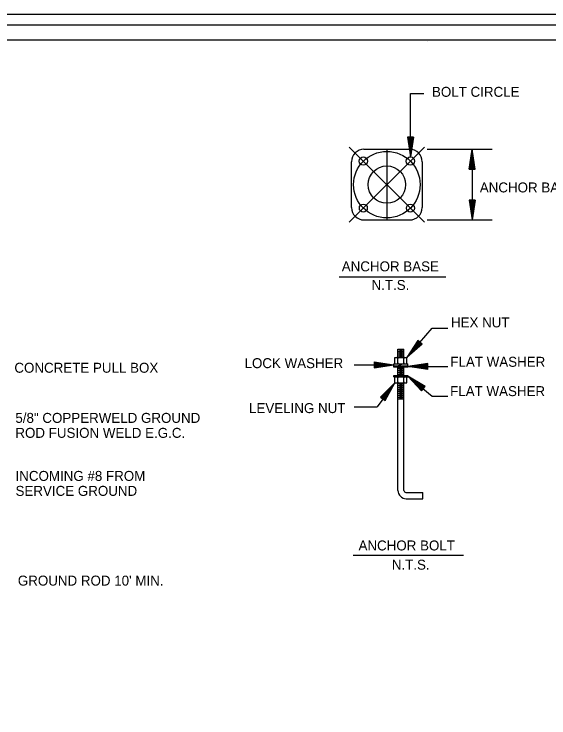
# Model space of a CAD drawing. Extents: x 1695551 to 1695718, y 544410 to 544516.
# Drawn here: x 1695602.6 to 1695642.8, y 544463.3 to 544516.2 of the extents above; entities that cross this region are included whole.
import ezdxf

# ---------------------------------------------------------------- set-up
doc = ezdxf.new("R2010")
doc.units = 0
for name, color, linetype in [('0_Plot Shape', 7, 'Continuous'), ('R_Border', 7, 'Continuous'), ('R_Draft', 7, 'Continuous'), ('R_No Plot', 7, 'Continuous')]:
    doc.layers.add(name, color=color, linetype=linetype)

msp = doc.modelspace()

# ---------------------------------------------------------------- linework, layer by layer
at = {"layer": '0_Plot Shape'}
msp.add_lwpolyline([(1695551.694, 544515.386), (1695716.694, 544515.386), (1695716.694, 544410.386), (1695551.694, 544410.386)], close=True, dxfattribs=at)
at = {"layer": 'R_Border'}
for p, q in [((1695557.469, 544514.251), (1695715.559, 544514.251)), ((1695633.729, 544514.121), (1695633.729, 544514.121)), ((1695633.729, 544514.121), (1695633.729, 544514.121))]:
    msp.add_line(p, q, dxfattribs=at)
at = {"layer": 'R_Draft'}
for p, q in [((1695632.418, 544505.451), (1695632.418, 544510.217)), ((1695632.418, 544510.217), (1695633.424, 544510.217)), ((1695632.193, 544506.951), (1695632.418, 544505.451)), ((1695632.643, 544506.951), (1695632.193, 544506.951)), ((1695632.23, 544506.951), (1695632.418, 544505.702)), ((1695632.268, 544506.951), (1695632.418, 544505.96)), ((1695632.306, 544506.951), (1695632.418, 544506.21)), ((1695632.344, 544506.951), (1695632.418, 544506.464)), ((1695632.382, 544506.951), (1695632.418, 544506.714)), ((1695632.643, 544506.951), (1695632.418, 544505.451)), ((1695632.49, 544506.951), (1695632.418, 544506.464)), ((1695632.567, 544506.951), (1695632.418, 544505.96)), ((1695632.605, 544506.951), (1695632.418, 544505.702)), ((1695632.529, 544506.951), (1695632.418, 544506.21)), ((1695632.453, 544506.951), (1695632.418, 544506.714)), ((1695633.478, 544500.543), (1695627.821, 544506.2)), ((1695627.821, 544500.543), (1695633.478, 544506.2)), ((1695628.931, 544506.027), (1695632.369, 544506.027)), ((1695630.65, 544506.027), (1695630.65, 544500.715)), ((1695633.681, 544506.027), (1695638.556, 544506.027)), ((1695636.831, 544504.527), (1695637.056, 544506.027)), ((1695636.869, 544504.527), (1695637.056, 544505.777)), ((1695637.056, 544506.027), (1695637.056, 544500.715)), ((1695637.281, 544504.527), (1695637.056, 544506.027)), ((1695637.244, 544504.527), (1695637.056, 544505.777)), ((1695627.994, 544501.652), (1695627.994, 544505.09)), ((1695633.306, 544505.09), (1695633.306, 544501.652)), ((1695636.907, 544504.527), (1695637.056, 544505.519)), ((1695636.944, 544504.527), (1695637.056, 544505.269)), ((1695636.983, 544504.527), (1695637.056, 544505.015)), ((1695637.205, 544504.527), (1695637.056, 544505.519)), ((1695637.168, 544504.527), (1695637.056, 544505.269)), ((1695637.13, 544504.527), (1695637.056, 544505.015)), ((1695636.831, 544504.527), (1695637.281, 544504.527)), ((1695637.021, 544504.527), (1695637.056, 544504.764)), ((1695637.091, 544504.527), (1695637.056, 544504.764)), ((1695636.831, 544502.215), (1695637.056, 544500.715)), ((1695637.281, 544502.215), (1695636.831, 544502.215)), ((1695636.869, 544502.215), (1695637.056, 544500.965)), ((1695636.907, 544502.215), (1695637.056, 544501.223)), ((1695636.944, 544502.215), (1695637.056, 544501.473)), ((1695636.983, 544502.215), (1695637.056, 544501.727)), ((1695637.021, 544502.215), (1695637.056, 544501.978)), ((1695637.281, 544502.215), (1695637.056, 544500.715)), ((1695637.129, 544502.215), (1695637.056, 544501.727)), ((1695637.205, 544502.215), (1695637.056, 544501.223)), ((1695637.244, 544502.215), (1695637.056, 544500.965)), ((1695637.168, 544502.215), (1695637.056, 544501.473)), ((1695637.091, 544502.215), (1695637.056, 544501.978)), ((1695628.931, 544500.715), (1695632.369, 544500.715)), ((1695633.681, 544500.715), (1695638.556, 544500.715)), ((1695635.071, 544496.414), (1695627.057, 544496.414)), ((1695632.16, 544490.378), (1695634.062, 544492.571)), ((1695634.062, 544492.571), (1695635.234, 544492.571)), ((1695632.969, 544491.661), (1695632.16, 544490.378)), ((1695633.31, 544491.367), (1695632.16, 544490.378)), ((1695632.997, 544491.636), (1695632.323, 544490.567)), ((1695633.281, 544491.391), (1695632.323, 544490.567)), ((1695633.026, 544491.611), (1695632.492, 544490.763)), ((1695633.252, 544491.416), (1695632.492, 544490.763)), ((1695633.055, 544491.587), (1695632.655, 544490.952)), ((1695633.224, 544491.441), (1695632.655, 544490.952)), ((1695633.084, 544491.562), (1695632.821, 544491.145)), ((1695633.194, 544491.466), (1695632.821, 544491.145)), ((1695633.31, 544491.367), (1695632.969, 544491.661)), ((1695633.113, 544491.537), (1695632.985, 544491.334)), ((1695633.166, 544491.491), (1695632.985, 544491.334)), ((1695631.485, 544491.003), (1695631.935, 544491.003)), ((1695631.485, 544490.378), (1695631.485, 544491.003)), ((1695631.485, 544490.858), (1695631.935, 544490.858)), ((1695631.485, 544490.714), (1695631.935, 544490.714)), ((1695631.597, 544490.928), (1695631.822, 544490.928)), ((1695631.597, 544490.783), (1695631.822, 544490.783)), ((1695631.935, 544490.378), (1695631.935, 544491.003)), ((1695631.26, 544489.904), (1695631.26, 544490.378)), ((1695631.26, 544490.378), (1695632.16, 544490.378)), ((1695631.485, 544490.57), (1695631.935, 544490.57)), ((1695631.485, 544490.426), (1695631.935, 544490.426)), ((1695631.485, 544489.904), (1695631.485, 544490.378)), ((1695631.597, 544490.639), (1695631.822, 544490.639)), ((1695631.597, 544490.495), (1695631.822, 544490.495)), ((1695631.935, 544489.904), (1695631.935, 544490.378)), ((1695632.16, 544489.904), (1695632.16, 544490.378)), ((1695628.185, 544489.829), (1695631.185, 544489.829)), ((1695629.685, 544490.054), (1695631.185, 544489.829)), ((1695629.685, 544490.054), (1695629.685, 544489.604)), ((1695629.685, 544490.016), (1695630.934, 544489.829)), ((1695629.685, 544489.978), (1695630.676, 544489.829)), ((1695629.685, 544489.94), (1695630.427, 544489.829)), ((1695629.685, 544489.901), (1695630.172, 544489.829)), ((1695629.685, 544489.864), (1695629.922, 544489.829)), ((1695629.685, 544489.604), (1695631.185, 544489.829)), ((1695629.685, 544489.755), (1695630.172, 544489.829)), ((1695629.685, 544489.679), (1695630.676, 544489.829)), ((1695629.685, 544489.641), (1695630.934, 544489.829)), ((1695629.685, 544489.717), (1695630.427, 544489.829)), ((1695629.685, 544489.793), (1695629.922, 544489.829)), ((1695631.185, 544489.653), (1695631.185, 544489.904)), ((1695631.185, 544489.904), (1695632.235, 544489.904)), ((1695631.185, 544489.753), (1695632.235, 544489.753)), ((1695631.185, 544489.658), (1695631.28, 544489.753)), ((1695631.185, 544489.711), (1695631.227, 544489.753)), ((1695632.235, 544489.653), (1695631.185, 544489.653)), ((1695631.233, 544489.653), (1695631.333, 544489.753)), ((1695631.286, 544489.653), (1695631.386, 544489.753)), ((1695631.339, 544489.653), (1695631.439, 544489.753)), ((1695631.392, 544489.653), (1695631.492, 544489.753)), ((1695631.445, 544489.653), (1695631.545, 544489.753)), ((1695631.485, 544489.028), (1695631.485, 544489.653)), ((1695631.487, 544489.753), (1695631.815, 544489.899)), ((1695631.498, 544489.653), (1695631.598, 544489.753)), ((1695631.551, 544489.653), (1695631.651, 544489.753)), ((1695631.604, 544489.653), (1695631.704, 544489.753)), ((1695631.657, 544489.653), (1695631.757, 544489.753)), ((1695631.71, 544489.653), (1695631.81, 544489.753)), ((1695631.763, 544489.653), (1695631.863, 544489.753)), ((1695631.816, 544489.653), (1695631.916, 544489.753)), ((1695631.869, 544489.653), (1695631.969, 544489.753)), ((1695631.922, 544489.653), (1695632.022, 544489.753)), ((1695631.935, 544489.028), (1695631.935, 544489.653)), ((1695631.975, 544489.653), (1695632.075, 544489.753)), ((1695632.028, 544489.653), (1695632.128, 544489.753)), ((1695632.081, 544489.653), (1695632.181, 544489.753)), ((1695632.134, 544489.653), (1695632.234, 544489.753)), ((1695632.187, 544489.653), (1695632.235, 544489.701)), ((1695633.735, 544489.928), (1695632.235, 544489.703)), ((1695632.235, 544489.653), (1695632.235, 544489.904)), ((1695632.235, 544489.703), (1695635.234, 544489.703)), ((1695633.735, 544489.478), (1695632.235, 544489.703)), ((1695633.735, 544489.891), (1695632.485, 544489.703)), ((1695633.735, 544489.516), (1695632.485, 544489.703)), ((1695633.735, 544489.853), (1695632.743, 544489.703)), ((1695633.735, 544489.554), (1695632.743, 544489.703)), ((1695633.735, 544489.815), (1695632.993, 544489.703)), ((1695633.735, 544489.592), (1695632.993, 544489.703)), ((1695633.735, 544489.777), (1695633.247, 544489.703)), ((1695633.735, 544489.631), (1695633.247, 544489.703)), ((1695633.735, 544489.739), (1695633.498, 544489.703)), ((1695633.735, 544489.668), (1695633.498, 544489.703)), ((1695633.735, 544489.478), (1695633.735, 544489.928)), ((1695631.485, 544489.56), (1695631.935, 544489.56)), ((1695631.485, 544489.416), (1695631.935, 544489.416)), ((1695631.485, 544489.272), (1695631.935, 544489.272)), ((1695631.485, 544489.128), (1695631.935, 544489.128)), ((1695631.597, 544489.63), (1695631.822, 544489.63)), ((1695631.597, 544489.485), (1695631.822, 544489.485)), ((1695631.597, 544489.341), (1695631.822, 544489.341)), ((1695631.597, 544489.197), (1695631.822, 544489.197)), ((1695631.185, 544488.928), (1695631.185, 544489.028)), ((1695631.185, 544489.028), (1695632.235, 544489.028)), ((1695631.185, 544488.978), (1695631.236, 544489.028)), ((1695631.185, 544488.928), (1695632.235, 544488.928)), ((1695631.189, 544488.928), (1695631.289, 544489.028)), ((1695631.242, 544488.928), (1695631.342, 544489.028)), ((1695631.26, 544488.455), (1695631.26, 544488.928)), ((1695631.295, 544488.928), (1695631.395, 544489.028)), ((1695631.348, 544488.928), (1695631.448, 544489.028)), ((1695631.401, 544488.928), (1695631.501, 544489.028)), ((1695631.454, 544488.928), (1695631.554, 544489.028)), ((1695631.485, 544488.455), (1695631.485, 544488.928)), ((1695631.507, 544488.928), (1695631.607, 544489.028)), ((1695631.56, 544488.928), (1695631.66, 544489.028)), ((1695631.597, 544489.053), (1695631.822, 544489.053)), ((1695631.613, 544488.928), (1695631.713, 544489.028)), ((1695631.666, 544488.928), (1695631.766, 544489.028)), ((1695631.719, 544488.928), (1695631.819, 544489.028)), ((1695631.772, 544488.928), (1695631.872, 544489.028)), ((1695631.825, 544488.928), (1695631.925, 544489.028)), ((1695631.878, 544488.928), (1695631.978, 544489.028)), ((1695631.931, 544488.928), (1695632.031, 544489.028)), ((1695631.935, 544488.455), (1695631.935, 544488.928)), ((1695631.984, 544488.928), (1695632.084, 544489.028)), ((1695632.037, 544488.928), (1695632.137, 544489.028)), ((1695632.09, 544488.928), (1695632.19, 544489.028)), ((1695632.143, 544488.928), (1695632.235, 544489.02)), ((1695632.16, 544488.455), (1695632.16, 544488.928)), ((1695632.196, 544488.928), (1695632.235, 544488.967)), ((1695632.235, 544488.928), (1695632.235, 544489.028)), ((1695632.235, 544488.978), (1695634.062, 544487.473)), ((1695633.251, 544487.852), (1695632.235, 544488.978)), ((1695633.536, 544488.199), (1695632.235, 544488.978)), ((1695633.274, 544487.881), (1695632.428, 544488.819)), ((1695633.513, 544488.17), (1695632.428, 544488.819)), ((1695633.488, 544488.141), (1695632.628, 544488.655)), ((1695633.299, 544487.91), (1695632.628, 544488.655)), ((1695631.26, 544488.455), (1695629.919, 544486.655)), ((1695630.172, 544487.397), (1695631.26, 544488.455)), ((1695630.202, 544487.375), (1695631.108, 544488.255)), ((1695630.5, 544487.148), (1695631.108, 544488.255)), ((1695630.53, 544487.125), (1695631.26, 544488.455)), ((1695631.26, 544488.455), (1695632.16, 544488.455)), ((1695631.485, 544480.378), (1695631.485, 544488.455)), ((1695631.485, 544488.407), (1695631.935, 544488.407)), ((1695631.485, 544488.262), (1695631.935, 544488.262)), ((1695631.485, 544488.118), (1695631.935, 544488.118)), ((1695631.597, 544488.332), (1695631.822, 544488.332)), ((1695631.597, 544488.187), (1695631.822, 544488.187)), ((1695631.935, 544480.371), (1695631.935, 544488.455)), ((1695633.322, 544487.939), (1695632.821, 544488.497)), ((1695633.464, 544488.112), (1695632.821, 544488.497)), ((1695633.44, 544488.082), (1695633.017, 544488.335)), ((1695633.347, 544487.969), (1695633.017, 544488.335)), ((1695633.416, 544488.053), (1695633.21, 544488.176)), ((1695633.371, 544487.998), (1695633.21, 544488.176)), ((1695633.251, 544487.852), (1695633.536, 544488.199)), ((1695630.232, 544487.352), (1695630.952, 544488.05)), ((1695630.262, 544487.329), (1695630.801, 544487.851)), ((1695630.293, 544487.305), (1695630.647, 544487.649)), ((1695630.41, 544487.217), (1695630.647, 544487.649)), ((1695630.44, 544487.193), (1695630.801, 544487.851)), ((1695630.47, 544487.171), (1695630.952, 544488.05)), ((1695631.485, 544487.974), (1695631.935, 544487.974)), ((1695631.485, 544487.83), (1695631.935, 544487.83)), ((1695631.485, 544487.685), (1695631.935, 544487.685)), ((1695631.485, 544487.541), (1695631.935, 544487.541)), ((1695631.597, 544488.043), (1695631.822, 544488.043)), ((1695631.597, 544487.899), (1695631.822, 544487.899)), ((1695631.597, 544487.755), (1695631.822, 544487.755)), ((1695631.597, 544487.61), (1695631.822, 544487.61)), ((1695630.172, 544487.397), (1695630.53, 544487.125)), ((1695630.323, 544487.283), (1695630.495, 544487.45)), ((1695630.379, 544487.24), (1695630.495, 544487.45)), ((1695631.485, 544487.397), (1695631.935, 544487.397)), ((1695631.485, 544487.253), (1695631.935, 544487.253)), ((1695631.597, 544487.466), (1695631.822, 544487.466)), ((1695631.597, 544487.322), (1695631.822, 544487.322)), ((1695634.062, 544487.473), (1695635.234, 544487.473)), ((1695628.185, 544486.655), (1695629.919, 544486.655)), ((1695632.085, 544480.221), (1695633.36, 544480.221)), ((1695633.36, 544479.753), (1695633.36, 544480.221)), ((1695632.11, 544479.753), (1695633.36, 544479.753)), ((1695636.414, 544475.487), (1695628.124, 544475.487))]:
    msp.add_line(p, q, dxfattribs=at)
for centre, radius in [((1695630.65, 544503.371), 2.5), ((1695628.882, 544505.139), 0.312), ((1695632.418, 544505.139), 0.312), ((1695630.65, 544503.371), 1.406), ((1695628.882, 544501.603), 0.3), ((1695632.418, 544501.603), 0.3)]:
    msp.add_circle(centre, radius, dxfattribs=at)
for centre, radius, start, end in [((1695628.931, 544505.09), 0.937, 90, 180), ((1695632.369, 544505.09), 0.937, 360, 90), ((1695628.931, 544501.652), 0.937, 180, 270), ((1695632.369, 544501.652), 0.937, 270, 0), ((1695631.41, 544490.303), 0.075, 0, 90), ((1695631.56, 544490.303), 0.075, 90, 180), ((1695631.86, 544490.303), 0.075, 0, 90), ((1695632.01, 544490.303), 0.075, 90, 180), ((1695631.41, 544489.979), 0.075, 270, 0), ((1695631.56, 544489.979), 0.075, 180, 270), ((1695631.86, 544489.979), 0.075, 270, 0), ((1695632.01, 544489.979), 0.075, 180, 270), ((1695631.41, 544488.853), 0.075, 0, 90), ((1695631.56, 544488.853), 0.075, 90, 180), ((1695631.86, 544488.853), 0.075, 0, 90), ((1695632.01, 544488.853), 0.075, 90, 180), ((1695631.41, 544488.53), 0.075, 270, 0), ((1695631.56, 544488.53), 0.075, 180, 270), ((1695631.86, 544488.53), 0.075, 270, 0), ((1695632.01, 544488.53), 0.075, 180, 270), ((1695632.11, 544480.378), 0.625, 180, 270), ((1695632.085, 544480.371), 0.15, 180, 270)]:
    msp.add_arc(centre, radius, start, end, dxfattribs=at)
at = {"layer": 'R_No Plot'}
msp.add_line((1695551.268, 544516.198), (1695717.935, 544516.198), dxfattribs=at)
msp.add_lwpolyline([(1695551.265, 544516.198), (1695717.935, 544516.198), (1695717.935, 544409.529), (1695551.265, 544409.529)], close=True, dxfattribs=at)

# ---------------------------------------------------------------- texts
at = {"layer": 'R_Draft'}
for s, p in [('BOLT CIRCLE', (1695634.041, 544509.975)), ('ANCHOR BASE SQUARE', (1695637.634, 544502.785)), ('ANCHOR BASE', (1695627.261, 544496.849)), ('N.T.S.', (1695629.5, 544495.45)), ('HEX NUT', (1695635.466, 544492.635)), ('LOCK WASHER', (1695619.957, 544489.569)), ('FLAT WASHER', (1695635.422, 544489.671)), ('CONCRETE PULL BOX', (1695602.661, 544489.224)), ('FLAT WASHER', (1695635.406, 544487.466)), ('LEVELING NUT', (1695620.294, 544486.19)), ('5/8" COPPERWELD GROUND ', (1695602.735, 544485.453)), ('ROD FUSION WELD E.G.C.', (1695602.735, 544484.328)), ('INCOMING #8 FROM ', (1695602.748, 544481.089)), ('SERVICE GROUND', (1695602.748, 544479.964)), ('ANCHOR BOLT', (1695628.521, 544475.858)), ('N.T.S.', (1695631.023, 544474.411)), ("GROUND ROD 10' MIN.", (1695602.921, 544473.215))]:
    msp.add_text(s, height=0.75, dxfattribs=at).set_placement(p)

doc.saveas('drawing.dxf')
